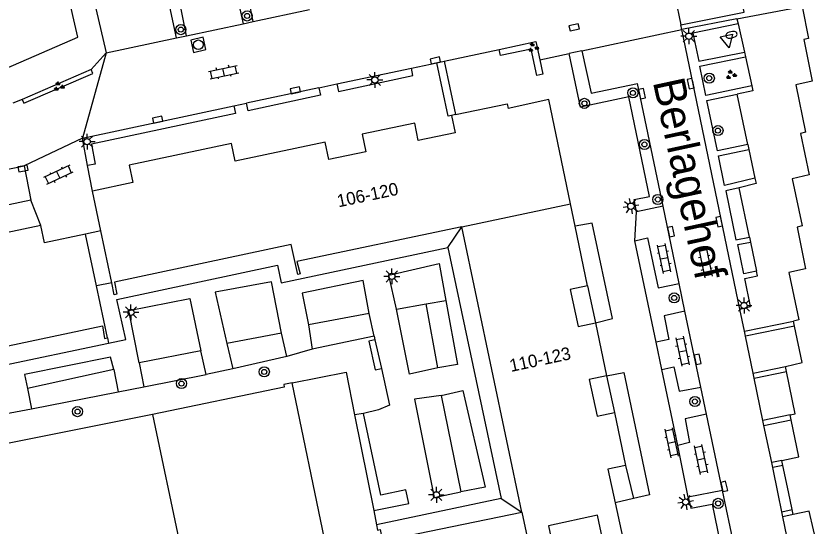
# Model space of a CAD drawing. Extents: x 132998 to 136004, y 396998 to 398512.
# Drawn here: x 133144.9 to 133208.3, y 397562.7 to 397603 of the extents above; entities that cross this region are included whole.
import ezdxf

# ---------------------------------------------------------------- set-up
doc = ezdxf.new("R2010")
doc.units = 0
for name, color, linetype in [('gg-afsc-erfafscheiding', 7, 'Continuous'), ('gg-anno-huisnummerreeks BGT', 7, 'Continuous'), ('gg-anno-openbare ruimte label', 7, 'Continuous'), ('gg-bbg-bijgebouw', 7, 'Continuous'), ('gg-bbg-gedigitaliseerde bijgebouw', 7, 'Continuous'), ('gg-bbg-hoofdgebouw', 7, 'Continuous'), ('gg-bbg-onder overbouw', 7, 'Continuous'), ('gg-bbg-pand overbouw', 7, 'Continuous'), ('gg-bbg-tussenscheiding', 7, 'Continuous'), ('gg-bbg-tussenscheiding niveau 01', 7, 'Continuous'), ('gg-knt-verharding', 7, 'Continuous'), ('gg-knt-verharding nz', 7, 'Continuous'), ('gt-grn-groengrens', 7, 'Continuous'), ('gt-grn-weggrens', 7, 'Continuous'), ('gt-symb-boom', 7, 'Continuous'), ('gt-symb-brandkraan', 7, 'Continuous'), ('gt-symb-groenvak', 7, 'Continuous'), ('gt-symb-klinker verharding', 7, 'Continuous'), ('gt-symb-kolk', 7, 'Continuous'), ('gt-symb-lichtmast', 7, 'Continuous'), ('gt-symb-rioolschacht', 7, 'Continuous'), ('gt-symb-waterafsluiter', 7, 'Continuous')]:
    doc.layers.add(name, color=color, linetype=linetype)

# ---------------------------------------------------------------- blocks, each defined once
blk = doc.blocks.new('gt0-GRVAK')
at = {"layer": 'gt-symb-groenvak'}
for p, q in [((-0.11, 0.189), (-0.228, 0.24)), ((-0.182, 0.153), (0.088, 0.153)), ((-0.091, 0.211), (-0.156, 0.322)), ((-0.047, 0.214), (-0.047, 0.393)), ((-0.004, 0.211), (0.061, 0.322)), ((0.015, 0.189), (0.133, 0.24)), ((0.262, -0.052), (0.197, 0.059)), ((0.305, -0.049), (0.305, 0.13)), ((0.349, -0.052), (0.414, 0.059)), ((-0.245, -0.228), (-0.363, -0.177)), ((-0.318, -0.264), (-0.047, -0.264)), ((-0.226, -0.206), (-0.291, -0.095)), ((-0.183, -0.203), (-0.183, -0.024)), ((-0.139, -0.206), (-0.074, -0.095)), ((-0.12, -0.228), (-0.002, -0.177)), ((0.243, -0.074), (0.125, -0.023)), ((0.17, -0.11), (0.441, -0.11)), ((0.368, -0.074), (0.486, -0.023))]:
    blk.add_line(p, q, dxfattribs=at)
blk = doc.blocks.new('gt0-KOLK')
at = {"layer": 'gt-symb-kolk'}
blk.add_lwpolyline([(0, 0), (0.375, 0), (0.375, 0.4), (-0.375, 0.4), (-0.375, 0), (0, 0)], dxfattribs=at)
blk = doc.blocks.new('gt0-LMAST')
at = {"layer": 'gt-symb-lichtmast'}
for p, q in [((-0.182, 0.173), (-0.447, 0.438)), ((-0.005, 0.246), (-0.005, 0.621)), ((0.172, 0.173), (0.437, 0.438)), ((-0.255, -0.004), (-0.63, -0.004)), ((-0.182, -0.181), (-0.447, -0.446)), ((-0.005, -0.254), (-0.005, -0.629)), ((0.437, -0.446), (0.172, -0.181)), ((0.245, -0.004), (0.62, -0.004))]:
    blk.add_line(p, q, dxfattribs=at)
blk.add_circle((-0.005, -0.004), 0.25, dxfattribs=at)
blk = doc.blocks.new('gt0-BOOM')
at = {"layer": 'gt-symb-boom'}
for radius in [0.4, 0.2]:
    blk.add_circle((0, 0), radius, dxfattribs=at)
blk = doc.blocks.new('gt0-KL1')
at = {"layer": 'gt-symb-klinker verharding'}
for p, q in [((-1.15, 0.3), (1.15, 0.3)), ((-1, -0.3), (-1, 0.3)), ((-0.5, 0.3), (-0.5, 0.45)), ((0, -0.3), (0, 0.3)), ((0.5, 0.3), (0.5, 0.45)), ((1, -0.3), (1, 0.3)), ((-1.15, -0.3), (1.15, -0.3)), ((-0.5, -0.45), (-0.5, -0.3)), ((0.5, -0.45), (0.5, -0.3))]:
    blk.add_line(p, q, dxfattribs=at)
blk = doc.blocks.new('gt0-RS')
at = {"layer": 'gt-symb-rioolschacht'}
blk.add_lwpolyline([(-0.5, -0.5), (0.5, -0.5), (0.5, 0.5), (-0.5, 0.5)], close=True, dxfattribs=at)
blk.add_circle((0, 0), 0.375, dxfattribs=at)
blk = doc.blocks.new('gt0-WAFSL')
at = {"layer": 'gt-symb-waterafsluiter'}
for p, q in [((-0.5, -0.333), (0, 0.667)), ((0, 0.667), (0.5, -0.333)), ((0.5, -0.333), (-0.5, -0.333))]:
    blk.add_line(p, q, dxfattribs=at)
blk = doc.blocks.new('gt0-BR')
at = {"layer": 'gt-symb-brandkraan'}
for centre, radius, start, end in [((-0.244, 0), 0.206, 107.56694, 252.43307), ((0.599, -2.664), 3, 106.89205, 107.56694), ((0, -0.691), 0.938, 73.10799, 106.89205), ((-0.599, -2.664), 3, 72.43309, 73.10799), ((0.244, 0), 0.206, 287.56695, 72.43309), ((0.599, 2.664), 3, 252.43307, 253.10797), ((0, 0.691), 0.938, 253.10797, 286.89206), ((-0.599, 2.664), 3, 286.89206, 287.56695)]:
    blk.add_arc(centre, radius, start, end, dxfattribs=at)

msp = doc.modelspace()

# ---------------------------------------------------------------- linework, layer by layer
at = {"layer": 'gg-afsc-erfafscheiding'}
for p, q in [((133173.546, 397571.924), (133172.357, 397571.616)), ((133172.357, 397571.616), (133171.65, 397571.529)), ((133171.65, 397571.529), (133173.155, 397563.955)), ((133173.155, 397563.955), (133173.377, 397562.838))]:
    msp.add_line(p, q, dxfattribs=at)
at = {"layer": 'gg-bbg-bijgebouw'}
msp.add_line((133169.26, 397561.74), (133166.71, 397574.05), dxfattribs=at)
msp.add_lwpolyline([(133166.71, 397574.05), (133166.05, 397573.92), (133166.09, 397573.71), (133155.67, 397571.55)], dxfattribs=at)
at = {"layer": 'gg-bbg-gedigitaliseerde bijgebouw'}
msp.add_line((133155.67, 397571.55), (133158.224, 397559.437), dxfattribs=at)
at = {"layer": 'gg-bbg-hoofdgebouw'}
for p, q in [((133179.626, 397595.236), (133179.311, 397595.17)), ((133151.603, 397586.045), (133150.94, 397589.2)), ((133189.068, 397586.412), (133188.698, 397588.185)), ((133190.05, 397581.71), (133189.068, 397586.412)), ((133151.254, 397581.699), (133150.39, 397585.79)), ((133152.462, 397581.954), (133151.603, 397586.045)), ((133190.67, 397578.8), (133191.55, 397574.61)), ((133206.411, 397578.538), (133206.33, 397578.93)), ((133205.762, 397574.938), (133205.68, 397575.33)), ((133192.17, 397571.7), (133193.04, 397567.52)), ((133206.142, 397571.128), (133206.06, 397571.52)), ((133205.492, 397567.528), (133205.41, 397567.92)), ((133205.932, 397565.438), (133205.492, 397567.528)), ((133206.228, 397564.032), (133205.932, 397565.438)), ((133206.31, 397563.64), (133206.228, 397564.032))]:
    msp.add_line(p, q, dxfattribs=at)
for points in [[(133144.21, 397598.59), (133144.08, 397598.888), (133149.791, 397601.353), (133148.929, 397605.036)], [(133207.006, 397603.785), (133207.501, 397601.26), (133207.13, 397601.17), (133207.81, 397597.89), (133206.5, 397597.59), (133207.28, 397593.85), (133206.88, 397593.75), (133207.55, 397590.48), (133206.22, 397590.17), (133207.01, 397586.45), (133206.61, 397586.35), (133207.28, 397583.06), (133205.95, 397582.76), (133206.74, 397579.03), (133206.33, 397578.93)], [(133188.698, 397588.185), (133186.98, 397596.418), (133183.77, 397595.712)], [(133179.626, 397595.236), (133183.69, 397596.09), (133183.77, 397595.712)], [(133179.311, 397595.17), (133179.6, 397593.8), (133176.681, 397593.2), (133176.41, 397594.56), (133172.24, 397593.68), (133172.53, 397592.3), (133169.6, 397591.68), (133169.311, 397593.06), (133162.21, 397591.56), (133161.91, 397592.95), (133153.84, 397591.25), (133154.13, 397589.88), (133150.94, 397589.2)], [(133146.86, 397586.49), (133142.72, 397585.6), (133143.01, 397584.23), (133140.1, 397583.6), (133139.81, 397584.97), (133135.62, 397584.1), (133135.91, 397582.73), (133133.01, 397582.11), (133132.72, 397583.48), (133128.54, 397582.59)], [(133150.39, 397585.79), (133147.14, 397585.12), (133146.86, 397586.49)], [(133190.05, 397581.71), (133188.69, 397581.42), (133189.311, 397578.51), (133190.67, 397578.8)], [(133205.68, 397575.33), (133207.01, 397575.65), (133206.411, 397578.538)], [(133206.06, 397571.52), (133206.46, 397571.59), (133205.762, 397574.938)], [(133191.55, 397574.61), (133190.19, 397574.32), (133190.82, 397571.41), (133192.17, 397571.7)], [(133205.41, 397567.92), (133206.75, 397568.21), (133206.142, 397571.128)], [(133193.04, 397567.52), (133191.66, 397567.24), (133192.234, 397564.562)], [(133192.234, 397564.562), (133193.17, 397560.19), (133191.625, 397559.861)], [(133208.256, 397560.977), (133207.57, 397563.91), (133206.31, 397563.64)]]:
    msp.add_lwpolyline(points, dxfattribs=at)
at = {"layer": 'gg-bbg-onder overbouw'}
for p, q in [((133184.871, 397563.83), (133180.11, 397586.38)), ((133152.12, 397577.6), (133151.254, 397581.699))]:
    msp.add_line(p, q, dxfattribs=at)
for points in [[(133180.11, 397586.38), (133167.091, 397583.64), (133167.35, 397582.67), (133167.15, 397582.62), (133166.64, 397584.98), (133152.68, 397582), (133152.86, 397581.06), (133152.66, 397581.01), (133152.462, 397581.954)], [(133132.829, 397574.54), (133151.72, 397578.54), (133151.9, 397577.56), (133152.12, 397577.6)], [(133173.46, 397562.42), (133173.66, 397562.46), (133173.85, 397561.56), (133184.871, 397563.83)]]:
    msp.add_lwpolyline(points, dxfattribs=at)
at = {"layer": 'gg-bbg-pand overbouw'}
for p, q in [((133179.019, 397584.741), (133183.215, 397564.91)), ((133152.462, 397581.954), (133151.254, 397581.699)), ((133133.115, 397573.176), (133152.206, 397577.193)), ((133183.215, 397564.91), (133173.377, 397562.838)), ((133173.377, 397562.838), (133173.46, 397562.42))]:
    msp.add_line(p, q, dxfattribs=at)
msp.add_lwpolyline([(133152.206, 397577.193), (133153.573, 397577.481), (133152.875, 397580.645), (133165.556, 397583.333), (133165.846, 397581.962), (133179.019, 397584.741)], dxfattribs=at)
at = {"layer": 'gg-bbg-tussenscheiding'}
msp.add_line((133180.11, 397586.38), (133188.698, 397588.185), dxfattribs=at)
for points in [[(133184.871, 397563.83), (133185.959, 397558.654), (133186.22, 397558.71)], [(133191.625, 397559.861), (133190.832, 397563.586), (133186.966, 397562.763), (133187.759, 397559.038)]]:
    msp.add_lwpolyline(points, dxfattribs=at)
at = {"layer": 'gg-bbg-tussenscheiding niveau 01'}
for p, q in [((133179.019, 397584.741), (133180.11, 397586.38)), ((133152.12, 397577.6), (133152.206, 397577.193)), ((133183.215, 397564.91), (133184.871, 397563.83))]:
    msp.add_line(p, q, dxfattribs=at)
at = {"layer": 'gg-knt-verharding'}
for p, q in [((133158.357, 397601.469), (133157.357, 397606.514)), ((133162.582, 397603.597), (133162.834, 397602.42)), ((133163.636, 397602.59), (133163.386, 397603.765)), ((133201.859, 397602.79), (133197.508, 397601.949)), ((133201.859, 397602.79), (133201.942, 397602.416)), ((133162.834, 397602.42), (133163.636, 397602.59)), ((133201.942, 397602.416), (133202.439, 397600.179)), ((133157.583, 397601.305), (133158.357, 397601.469)), ((133202.087, 397579.869), (133197.508, 397601.949)), ((133152.018, 397600.122), (133157.583, 397601.305)), ((133189.603, 397600.281), (133188.612, 397600.061)), ((133202.439, 397600.179), (133202.522, 397599.805)), ((133202.522, 397599.805), (133203.033, 397597.505)), ((133176.131, 397598.909), (133178.137, 397599.337)), ((133178.137, 397599.337), (133178.724, 397599.462)), ((133178.724, 397599.462), (133179.626, 397595.236)), ((133150.824, 397598.795), (133145.385, 397596.435)), ((133170.255, 397597.656), (133176.131, 397598.909)), ((133196.014, 397588.014), (133193.986, 397597.699)), ((133168.832, 397597.353), (133163.109, 397596.133)), ((133168.832, 397597.353), (133170.255, 397597.656)), ((133202.719, 397592.887), (133201.884, 397596.864)), ((133150.15, 397593.37), (133162.104, 397595.919)), ((133162.104, 397595.919), (133163.109, 397596.133)), ((133150.557, 397591.22), (133150.15, 397593.37)), ((133202.719, 397592.887), (133202.801, 397592.494)), ((133202.801, 397592.494), (133203.281, 397590.21)), ((133145.53, 397591.2), (133146.07, 397588.47)), ((133150.94, 397589.2), (133150.557, 397591.22)), ((133202.85, 397585.565), (133202.038, 397589.462)), ((133196.014, 397588.014), (133193.929, 397587.567)), ((133197.293, 397581.902), (133196.014, 397588.014)), ((133195.466, 397577.265), (133193.786, 397585.266)), ((133202.85, 397585.565), (133202.931, 397585.173)), ((133202.931, 397585.173), (133203.408, 397582.883)), ((133195.644, 397581.547), (133197.293, 397581.902)), ((133197.751, 397579.717), (133197.293, 397581.902)), ((133173.187, 397577.739), (133172.8, 397579.533)), ((133197.751, 397579.717), (133196.109, 397579.35)), ((133199.007, 397573.715), (133197.751, 397579.717)), ((133202.449, 397578.125), (133202.087, 397579.869)), ((133167.995, 397578.622), (133168.305, 397576.699)), ((133202.53, 397577.733), (133202.449, 397578.125)), ((133166.296, 397576.135), (133165.869, 397577.98)), ((133173.187, 397577.739), (133173.253, 397577.447)), ((133173.253, 397577.447), (133173.76, 397575.195)), ((133203.137, 397574.803), (133202.53, 397577.733)), ((133161.562, 397577.168), (133162.025, 397575.152)), ((133159.914, 397574.701), (133159.511, 397576.586)), ((133168.305, 397576.699), (133166.296, 397576.135)), ((133154.632, 397575.621), (133155, 397573.739)), ((133152.623, 397575.11), (133152.969, 397573.342)), ((133162.025, 397575.152), (133159.914, 397574.701)), ((133197.189, 397569.098), (133195.924, 397575.109)), ((133203.219, 397574.411), (133203.137, 397574.803)), ((133203.911, 397571.074), (133203.219, 397574.411)), ((133145.794, 397573.595), (133146.107, 397571.998)), ((133152.969, 397573.342), (133155, 397573.739)), ((133197.303, 397573.399), (133199.007, 397573.715)), ((133199.457, 397571.566), (133199.007, 397573.715)), ((133144.02, 397571.59), (133146.107, 397571.998)), ((133199.457, 397571.566), (133197.752, 397571.217)), ((133200.715, 397565.554), (133199.457, 397571.566)), ((133203.992, 397570.682), (133203.911, 397571.074)), ((133204.6, 397567.752), (133203.992, 397570.682)), ((133204.681, 397567.36), (133204.6, 397567.752)), ((133205.11, 397565.289), (133204.681, 397567.36)), ((133200.715, 397565.554), (133198.01, 397565.018)), ((133202.954, 397554.86), (133200.715, 397565.554)), ((133193.679, 397564.91), (133192.234, 397564.562)), ((133205.407, 397563.861), (133205.11, 397565.289)), ((133205.488, 397563.469), (133205.407, 397563.861)), ((133206.098, 397560.524), (133205.488, 397563.469))]:
    msp.add_line(p, q, dxfattribs=at)
for points in [[(133156.581, 397605.984), (133151.204, 397603.616), (133152.018, 397600.122)], [(133183.075, 397600.393), (133185.978, 397601.001), (133186.279, 397599.562)], [(133186.279, 397599.562), (133186.517, 397598.428), (133186.033, 397598.33), (133185.594, 397600.416), (133183.174, 397599.908), (133183.075, 397600.393)], [(133189.603, 397600.281), (133190.33, 397596.928), (133193.986, 397597.699)], [(133193.929, 397587.567), (133193.73, 397588.52), (133194.938, 397588.778), (133193.32, 397596.648), (133189.501, 397595.834), (133188.612, 397600.061)], [(133145.385, 397596.435), (133145.52, 397596.13), (133150.97, 397598.472), (133150.824, 397598.795)], [(133203.033, 397597.505), (133203.118, 397597.124), (133201.884, 397596.864)], [(133132.063, 397587.359), (133137.05, 397589.46), (133145.53, 397591.2)], [(133203.281, 397590.21), (133203.37, 397589.784), (133202.038, 397589.462)], [(133146.07, 397588.47), (133132.41, 397585.59), (133132.063, 397587.359)], [(133190.67, 397578.8), (133192.03, 397579.144), (133190.416, 397586.66), (133189.068, 397586.412)], [(133193.786, 397585.266), (133194.787, 397585.495), (133195.644, 397581.547)], [(133174.963, 397579.86), (133174.35, 397582.563), (133178.331, 397583.466), (133178.855, 397580.563)], [(133202.087, 397579.869), (133202.929, 397580.09), (133202.48, 397582.281), (133203.486, 397582.509), (133203.408, 397582.883)], [(133165.869, 397577.98), (133165.087, 397582.039), (133160.633, 397581.206), (133161.562, 397577.168)], [(133172.8, 397579.533), (133172.324, 397582.137), (133167.497, 397581.141), (133167.995, 397578.622)], [(133154.632, 397575.621), (133153.821, 397579.762), (133158.631, 397580.704), (133159.511, 397576.586)], [(133178.855, 397580.563), (133179.768, 397575.509), (133178.213, 397575.229)], [(133178.213, 397575.229), (133175.975, 397574.738), (133174.963, 397579.86)], [(133196.109, 397579.35), (133196.461, 397577.485), (133195.466, 397577.265)], [(133152.623, 397575.11), (133152.36, 397576.07), (133145.557, 397574.709), (133145.794, 397573.595)], [(133173.76, 397575.195), (133174.417, 397572.279), (133173.546, 397571.924)], [(133191.55, 397574.61), (133192.926, 397574.855), (133194.949, 397565.215), (133193.679, 397564.91)], [(133195.924, 397575.109), (133196.882, 397575.319), (133197.303, 397573.399)], [(133178.493, 397573.058), (133176.373, 397572.757), (133177.946, 397565.005), (133180.041, 397565.43)], [(133178.493, 397573.058), (133180.192, 397573.451), (133181.96, 397565.82), (133180.041, 397565.43)], [(133173.155, 397563.955), (133175.93, 397564.506), (133175.694, 397565.611), (133173.728, 397565.166), (133172.357, 397571.616)], [(133197.752, 397571.217), (133198.104, 397569.335), (133197.189, 397569.098)], [(133198.01, 397565.018), (133198.224, 397564.147), (133199.902, 397564.462), (133201.75, 397555.498), (133200.145, 397555.153), (133200.262, 397554.292), (133201.7, 397554.595)]]:
    msp.add_lwpolyline(points, dxfattribs=at)
at = {"layer": 'gg-knt-verharding nz'}
for p, q in [((133195.941, 397609.511), (133197.431, 397602.321)), ((133163.636, 397602.59), (133168.087, 397603.535)), ((133158.357, 397601.469), (133162.834, 397602.42))]:
    msp.add_line(p, q, dxfattribs=at)
msp.add_lwpolyline([(133197.431, 397602.321), (133202.422, 397603.317), (133200.902, 397610.497), (133199.801, 397610.201), (133199.761, 397610.349)], dxfattribs=at)
at = {"layer": 'gt-grn-groengrens'}
for p, q in [((133157.583, 397601.305), (133156.581, 397605.984)), ((133190.05, 397581.71), (133190.67, 397578.8)), ((133177.3, 397580.283), (133178.855, 397580.563)), ((133174.963, 397579.86), (133177.3, 397580.283)), ((133178.213, 397575.229), (133177.3, 397580.283)), ((133172.8, 397579.533), (133167.995, 397578.622)), ((133202.449, 397578.125), (133206.33, 397578.93)), ((133206.411, 397578.538), (133202.53, 397577.733)), ((133165.869, 397577.98), (133161.562, 397577.168)), ((133173.187, 397577.739), (133168.305, 397576.699)), ((133159.511, 397576.586), (133154.632, 397575.621)), ((133166.296, 397576.135), (133162.025, 397575.152)), ((133152.623, 397575.11), (133145.794, 397573.595)), ((133203.137, 397574.803), (133205.68, 397575.33)), ((133203.219, 397574.411), (133205.762, 397574.938)), ((133155, 397573.739), (133159.914, 397574.701)), ((133191.55, 397574.61), (133192.17, 397571.7)), ((133146.107, 397571.998), (133152.969, 397573.342)), ((133178.493, 397573.058), (133180.041, 397565.43)), ((133155.67, 397571.55), (133131.839, 397566.803)), ((133206.06, 397571.52), (133203.911, 397571.074)), ((133203.992, 397570.682), (133206.142, 397571.128)), ((133205.41, 397567.92), (133204.6, 397567.752)), ((133193.04, 397567.52), (133193.679, 397564.91)), ((133205.492, 397567.528), (133204.681, 397567.36)), ((133205.407, 397563.861), (133206.228, 397564.032)), ((133206.31, 397563.64), (133205.488, 397563.469))]:
    msp.add_line(p, q, dxfattribs=at)
for points in [[(133201.942, 397602.416), (133198.369, 397601.675), (133198.834, 397599.449), (133202.439, 397600.179)], [(133203.033, 397597.505), (133199.396, 397596.751), (133198.915, 397599.057), (133202.522, 397599.805)], [(133179.311, 397595.17), (133179.039, 397595.111), (133178.137, 397599.337)], [(133170.255, 397597.656), (133170.38, 397597.07), (133176.256, 397598.322), (133176.131, 397598.909)], [(133168.832, 397597.353), (133168.957, 397596.766), (133163.234, 397595.546), (133163.109, 397596.133)], [(133202.719, 397592.887), (133200.309, 397592.378), (133199.479, 397596.357), (133201.884, 397596.864)], [(133162.104, 397595.919), (133162.229, 397595.332), (133150.849, 397592.905), (133151.147, 397591.332), (133150.557, 397591.22)], [(133203.281, 397590.21), (133200.883, 397589.63), (133200.391, 397591.986), (133202.801, 397592.494)], [(133202.038, 397589.462), (133200.971, 397589.204), (133201.778, 397585.341), (133202.85, 397585.565)], [(133203.408, 397582.883), (133202.4, 397582.673), (133201.93, 397584.964), (133202.931, 397585.173)], [(133173.253, 397577.447), (133172.765, 397577.337), (133173.272, 397575.086), (133173.76, 397575.195)], [(133166.71, 397574.05), (133170.98, 397574.899), (133171.65, 397571.529)]]:
    msp.add_lwpolyline(points, dxfattribs=at)
at = {"layer": 'gt-grn-weggrens'}
for p, q in [((133201.859, 397602.79), (133207.006, 397603.785)), ((133197.508, 397601.949), (133197.431, 397602.321)), ((133189.603, 397600.281), (133197.508, 397601.949)), ((133178.724, 397599.462), (133183.075, 397600.393)), ((133152.018, 397600.122), (133150.15, 397593.37)), ((133152.018, 397600.122), (133150.824, 397598.795)), ((133186.279, 397599.562), (133188.612, 397600.061)), ((133145.385, 397596.435), (133144.648, 397596.139)), ((133150.15, 397593.37), (133145.53, 397591.2)), ((133146.86, 397586.49), (133146.07, 397588.47)), ((133193.786, 397585.266), (133193.929, 397587.567)), ((133151.603, 397586.045), (133150.39, 397585.79)), ((133195.924, 397575.109), (133195.466, 397577.265)), ((133198.01, 397565.018), (133197.189, 397569.098))]:
    msp.add_line(p, q, dxfattribs=at)

# ---------------------------------------------------------------- block references
at = {"layer": 'gt-symb-boom'}
for p in [(133163.15, 397603.03), (133157.919, 397601.948), (133199.669, 397598.116), (133193.642, 397596.951), (133189.799, 397596.127), (133200.357, 397593.974), (133194.546, 397592.879), (133195.602, 397588.53), (133196.897, 397580.756), (133164.513, 397574.915), (133157.973, 397573.99), (133198.538, 397572.575), (133149.758, 397571.776), (133200.367, 397564.528)]:
    msp.add_blockref('gt0-BOOM', p, dxfattribs=at)
at = {"layer": 'gt-symb-brandkraan', "rotation": -167.52092819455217}
msp.add_blockref('gt0-BR', (133201.418, 397601.546), dxfattribs=at)
at = {"layer": 'gt-symb-groenvak'}
for p in [(133185.754, 397600.532), (133201.38, 397598.374), (133148.276, 397597.455)]:
    msp.add_blockref('gt0-GRVAK', p, dxfattribs=at)
at = {"layer": 'gt-symb-klinker verharding'}
for p, rotation in [((133161.302, 397598.595), 12.00670830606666), ((133148.229, 397590.482), -154.84462756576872), ((133196.115, 397583.869), 101.82670392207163), ((133199.366, 397583.541), -78.28547478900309), ((133197.556, 397576.548), -78.17329607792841), ((133196.706, 397569.321), 101.82670392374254), ((133199.033, 397567.999), 101.82670392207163)]:
    msp.add_blockref('gt0-KL1', p, dxfattribs=dict(at, rotation=rotation))
at = {"layer": 'gt-symb-kolk'}
for p, rotation in [((133188.945, 397602.327), -166.53322310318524), ((133178.072, 397599.323), 13.007504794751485), ((133198.384, 397597.716), 102.29885516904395), ((133167.002, 397596.963), 12.06274602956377), ((133194.163, 397596.841), -77.64517308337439), ((133156.119, 397594.642), 11.590736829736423), ((133145.412, 397591.176), -168.2854747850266), ((133200.645, 397586.824), 102.29885516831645), ((133196.443, 397585.955), -77.75714042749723), ((133198.557, 397575.865), -77.7011448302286), ((133200.652, 397565.822), -77.64517308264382)]:
    msp.add_blockref('gt0-KOLK', p, dxfattribs=dict(at, rotation=rotation))
at = {"layer": 'gt-symb-lichtmast'}
for p in [(133198.065, 397601.436), (133173.253, 397597.976), (133150.517, 397593.104), (133174.593, 397582.46), (133202.42, 397580.157), (133153.981, 397579.623), (133178.112, 397565.203)]:
    msp.add_blockref('gt0-LMAST', p, dxfattribs=at)
for p, rotation in [((133193.481, 397587.998), -79.92566726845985), ((133197.803, 397564.638), -79.92566727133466)]:
    msp.add_blockref('gt0-LMAST', p, dxfattribs=dict(at, rotation=rotation))
at = {"layer": 'gt-symb-rioolschacht', "rotation": 13.41107184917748}
msp.add_blockref('gt0-RS', (133159.302, 397600.756), dxfattribs=at)
at = {"layer": 'gt-symb-waterafsluiter', "rotation": -167.5209281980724}
msp.add_blockref('gt0-WAFSL', (133201.093, 397601.166), dxfattribs=at)

# ---------------------------------------------------------------- texts
at = {"layer": 'gg-anno-huisnummerreeks BGT'}
for s, rotation, p in [('106-120', 11.9, (133170.374, 397587.907)), ('110-123', 12, (133184.002, 397574.906))]:
    msp.add_text(s, height=1, rotation=rotation, dxfattribs=at).set_placement(p)
at = {"layer": 'gg-anno-openbare ruimte label'}
msp.add_text('Berlagehof', height=2.5, rotation=282.2, dxfattribs=at).set_placement((133195.2, 397597.835))

doc.saveas('drawing.dxf')
